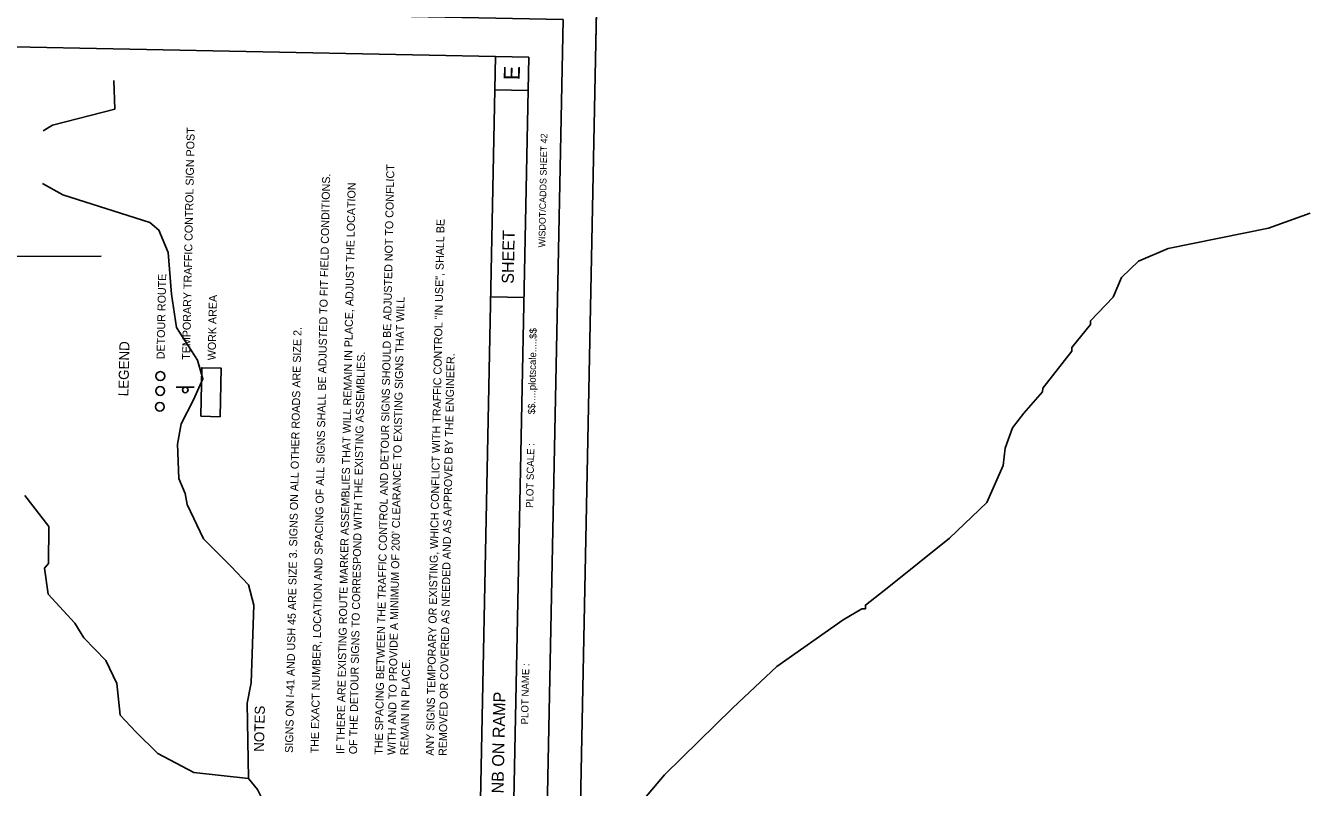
# Model space of a CAD drawing. Extents: x 331323 to 388339, y 121519 to 205315.
# Drawn here: x 363256 to 374815, y 143362 to 150213 of the extents above; entities that cross this region are included whole.
import ezdxf

# ---------------------------------------------------------------- set-up
doc = ezdxf.new("R2010")
doc.units = 0
for name, color, linetype in [('CA-TEXT', 7, 'Continuous'), ('CE-TOPO-CONC-SLAB', 7, 'Continuous'), ('Level 3', 7, 'Continuous'), ('Level 57', 7, 'Continuous'), ('P_RDWY_Text', 7, 'Continuous'), ('P_TC', 7, 'Continuous'), ('PLT_Sheet_Border', 7, 'Continuous'), ('PLT_Sheet_Info', 7, 'Continuous'), ('SIGNS-POLES', 7, 'Continuous')]:
    doc.layers.add(name, color=color, linetype=linetype)

msp = doc.modelspace()

# ---------------------------------------------------------------- linework, layer by layer
at = {"layer": 'CE-TOPO-CONC-SLAB'}
for centre in [(364468, 147061), (364466, 146928), (364463, 146785)]:
    msp.add_circle(centre, 40.2, dxfattribs=at)
at = {"layer": 'Level 3'}
msp.add_line((363934, 148140), (355745, 148126), dxfattribs=at)
at = {"layer": 'Level 57'}
for points in [[(364048, 149719), (364057, 149462), (363496, 149317), (363413, 149268)], [(363408, 148793), (363591, 148691), (364372, 148442), (364455, 148375), (364537, 148174), (364567, 147799), (364614, 147499), (364803, 147205), (364851, 147038), (364766, 146847), (364656, 146631), (364621, 146448), (364635, 146140), (364692, 146006), (364708, 145906), (364855, 145596), (365103, 145352), (365260, 145184), (365308, 145000), (365285, 144301), (365250, 144118), (365260, 143443)], [(373116, 147947), (373268, 148095), (373536, 148209), (374438, 148393), (374815, 148526)], [(370812, 144967), (370812, 145001), (371022, 145165), (371569, 145602), (371905, 145924), (372050, 146256), (372068, 146414), (372136, 146597), (372238, 146729), (372406, 146920), (372407, 146953), (372668, 147284), (372669, 147317), (372837, 147524), (372838, 147557), (373040, 147772), (373116, 147947)], [(363249, 145986), (363463, 145709), (363460, 145376), (363426, 145334), (363458, 145101), (363697, 144840), (363779, 144706), (363977, 144504), (364076, 144295), (364106, 144011)], [(367015, 141052), (367166, 141192), (367293, 141374), (367696, 141687), (367772, 141761), (367857, 141961), (367874, 142044), (367928, 142418), (367979, 142535), (368081, 142684), (368282, 142840), (368676, 143087), (369005, 143475), (369620, 144078), (370015, 144450), (370611, 144869), (370779, 144968), (370812, 144967)], [(364106, 144011), (364247, 143860), (364445, 143667), (364769, 143497), (365260, 143443)], [(364906, 142137), (364925, 142346), (365009, 142461), (365403, 142641), (365487, 142740), (365490, 143049), (365343, 143342), (365260, 143443)]]:
    msp.add_lwpolyline(points, dxfattribs=at)
at = {"layer": 'P_RDWY_Text'}
msp.add_lwpolyline([(354791, 130528), (355202, 150924), (368399, 150658), (367988, 130262)], close=True, dxfattribs=at)
at = {"layer": 'P_TC'}
msp.add_lwpolyline([(364831, 146700), (364840, 147136), (365014, 147133), (365005, 146696)], close=True, dxfattribs=at)
at = {"layer": 'PLT_Sheet_Border'}
for points in [[(367988, 130262), (368399, 150658), (355202, 150924), (354791, 130528)], [(367691, 130412), (368091, 150268), (355494, 150522), (355094, 130666)]]:
    msp.add_lwpolyline(points, close=True, dxfattribs=at)
at = {"layer": 'PLT_Sheet_Info'}
for p, q in [((368387, 150058), (368399, 150658)), ((367784, 149929), (355787, 150171)), ((367104, 131039), (367484, 149935)), ((367404, 131033), (367784, 149929)), ((367778, 149629), (367478, 149635)), ((367741, 147769), (367441, 147775))]:
    msp.add_line(p, q, dxfattribs=at)
at = {"layer": 'SIGNS-POLES'}
for p, q in [((364609, 146963), (364690, 146962)), ((364691, 146962), (364772, 146961))]:
    msp.add_line(p, q, dxfattribs=at)
msp.add_circle((364692, 146937), 25, dxfattribs=at)

# ---------------------------------------------------------------- texts
at = {"layer": 'CA-TEXT'}
for s, height, rotation, p in [('TEMPORARY TRAFFIC CONTROL SIGN POST', 72, 88.8468, (364735, 147207)), ('THE SPACING BETWEEN THE TRAFFIC CONTROL AND DETOUR SIGNS SHOULD BE ADJUSTED NOT TO CONFLICT', 72, 88.8462, (366467, 143655)), ('THE EXACT NUMBER, LOCATION AND SPACING OF ALL SIGNS SHALL BE ADJUSTED TO FIT FIELD CONDITIONS.', 72, 88.8462, (365891, 143667)), ('IF THERE ARE EXISTING ROUTE MARKER ASSEMBLIES THAT WILL REMAIN IN PLACE, ADJUST THE LOCATION ', 72, 88.8462, (366122, 143662)), ('ANY SIGNS TEMPORARY OR EXISTING, WHICH CONFLICT WITH TRAFFIC CONTROL "IN USE", SHALL BE', 72, 88.8462, (366928, 143646)), ('DETOUR ROUTE', 72, 88.8468, (364505, 147212)), ('WORK AREA', 72, 88.8468, (364965, 147203)), ("WITH AND TO PROVIDE A MINIMUM OF 200' CLEARANCE TO EXISTING SIGNS THAT WILL", 72, 88.8462, (366582, 143653)), ('SIGNS ON I-41 AND USH 45 ARE SIZE 3. SIGNS ON ALL OTHER ROADS ARE SIZE 2.', 72, 88.8462, (365661, 143672)), ('LEGEND', 90, 88.8468, (364180, 146879)), ('OF THE DETOUR SIGNS TO CORRESPOND WITH THE EXISTING ASSEMBLIES. ', 72, 88.8462, (366237, 143660)), ('REMOVED OR COVERED AS NEEDED AND AS APPROVED BY THE ENGINEER.', 72, 88.8462, (367043, 143644)), ('REMAIN IN PLACE.', 72, 88.8462, (366698, 143651)), ('NOTES', 90, 88.8468, (365400, 143681))]:
    msp.add_text(s, height=height, rotation=rotation, dxfattribs=at).set_placement(p)
at = {"layer": 'PLT_Sheet_Info'}
for s, height, p in [('E', 144, (367701, 149722)), ('WISDOT/CADDS SHEET 42', 60, (367930, 148218)), ('SHEET ', 108, (367647, 147891)), ('$$.....plotscale.....$$', 64.8, (367839, 146717)), ('PLOT SCALE : ', 64.8, (367822, 145875)), ('PLOT NAME :                      ', 64.8, (367777, 143928)), ('DETOUR ROUTE - STH 145 NB ON RAMP                    ', 108, (367517, 141413))]:
    msp.add_text(s, height=height, rotation=88.8462, dxfattribs=at).set_placement(p)

doc.saveas('drawing.dxf')
